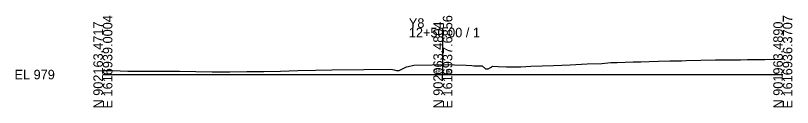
# Model space of a CAD drawing. Extents: x -26 to 1403, y -10 to 3025.
# Drawn here: x -25.7 to 202.8, y 2490.3 to 2517.4 of the extents above; entities that cross this region are included whole.
import ezdxf

# ---------------------------------------------------------------- set-up
doc = ezdxf.new("R2010")
doc.units = 0
for name, color, linetype in [('Exist Cross Section Cell', 7, 'Continuous'), ('Exist XS Center Line Elevation Label', 7, 'Continuous'), ('Exist XS Ground Line', 7, 'Continuous')]:
    doc.layers.add(name, color=color, linetype=linetype)

msp = doc.modelspace()

# ---------------------------------------------------------------- linework, layer by layer
at = {"layer": 'Exist Cross Section Cell'}
for p, q in [((100, 2500), (100, 2513.76)), ((0, 2500), (100, 2500)), ((100, 2500), (200, 2500))]:
    msp.add_line(p, q, dxfattribs=at)
at = {"layer": 'Exist XS Ground Line'}
for p, q in [((89.77, 2502.36), (91.48, 2502.75)), ((91.48, 2502.75), (96.85, 2502.86)), ((96.85, 2502.86), (99.99, 2502.94)), ((99.99, 2502.94), (106.84, 2502.74)), ((106.84, 2502.74), (108.57, 2502.68)), ((108.57, 2502.68), (109.09, 2502.59)), ((109.09, 2502.59), (111.58, 2502.54)), ((111.58, 2502.54), (112.54, 2501.69)), ((114.05, 2502.05), (114.61, 2502.43)), ((114.61, 2502.43), (116.3, 2502.35)), ((122.95, 2502.31), (125.87, 2502.49)), ((125.87, 2502.49), (132.53, 2502.71)), ((132.53, 2502.71), (137.47, 2502.9)), ((137.47, 2502.9), (142.45, 2503.17)), ((142.45, 2503.17), (146.74, 2503.3)), ((146.74, 2503.3), (149.42, 2503.5)), ((149.42, 2503.5), (151.27, 2503.55)), ((151.27, 2503.55), (156.01, 2503.7)), ((156.01, 2503.7), (158.21, 2503.77)), ((158.21, 2503.77), (160.66, 2503.84)), ((160.66, 2503.84), (163.45, 2503.92)), ((163.45, 2503.92), (166.74, 2503.99)), ((166.74, 2503.99), (170.16, 2504.08)), ((170.16, 2504.08), (171.53, 2504.11)), ((171.53, 2504.11), (180.16, 2504.3)), ((180.16, 2504.3), (181.97, 2504.33)), ((181.97, 2504.33), (187.51, 2504.38)), ((187.51, 2504.38), (189.58, 2504.42)), ((189.58, 2504.42), (194.69, 2504.41)), ((194.69, 2504.41), (199.48, 2504.56)), ((199.48, 2504.56), (200, 2504.59)), ((0, 2501.15), (2.84, 2501.15)), ((2.84, 2501.15), (7.3, 2500.99)), ((7.3, 2500.99), (12.71, 2500.97)), ((12.71, 2500.97), (17.3, 2501.03)), ((17.3, 2501.03), (22.58, 2500.97)), ((22.58, 2500.97), (27.3, 2500.92)), ((27.3, 2500.92), (32.15, 2500.84)), ((32.15, 2500.84), (37.31, 2500.83)), ((37.31, 2500.83), (42.33, 2500.87)), ((42.33, 2500.87), (47.31, 2500.87)), ((47.31, 2500.87), (52.2, 2501.02)), ((52.2, 2501.02), (57.31, 2501.15)), ((57.31, 2501.15), (62.56, 2501.27)), ((62.56, 2501.27), (67.31, 2501.41)), ((67.31, 2501.41), (76.75, 2501.49)), ((76.75, 2501.49), (84.74, 2501.57)), ((84.74, 2501.57), (85.69, 2501.36)), ((85.69, 2501.36), (86.4, 2501.2)), ((86.4, 2501.2), (86.75, 2501.2)), ((86.75, 2501.2), (87.15, 2501.2)), ((87.15, 2501.2), (88.68, 2501.96)), ((88.68, 2501.96), (89.27, 2502.25)), ((89.27, 2502.25), (89.77, 2502.36)), ((112.54, 2501.69), (113.29, 2501.69)), ((113.29, 2501.69), (114.05, 2502.05)), ((116.3, 2502.35), (118.77, 2502.23)), ((118.77, 2502.23), (121.3, 2502.25)), ((121.3, 2502.25), (122.95, 2502.31))]:
    msp.add_line(p, q, dxfattribs=at)

# ---------------------------------------------------------------- texts
at = {"layer": 'Exist Cross Section Cell'}
for s, p in [('E 1616939.0004', (2.8, 2490)), ('E 1616937.6856', (102.8, 2490)), ('E 1616936.3707', (202.8, 2490)), ('N 902163.4717', (0, 2490)), ('N 902063.4804', (100, 2490)), ('N 901963.4890', (200, 2490))]:
    msp.add_text(s, height=2.8, rotation=90, dxfattribs=at).set_placement(p)
for s, p in [('Y8', (90, 2513.76)), ('12+50.00 / 1', (90, 2510.96)), ('EL 979', (-26, 2498.6))]:
    msp.add_text(s, height=2.8, dxfattribs=at).set_placement(p)
at = {"layer": 'Exist XS Center Line Elevation Label'}
msp.add_text('981.94', height=1.25, dxfattribs=at).set_placement((97.45, 2500.32))

doc.saveas('drawing.dxf')
